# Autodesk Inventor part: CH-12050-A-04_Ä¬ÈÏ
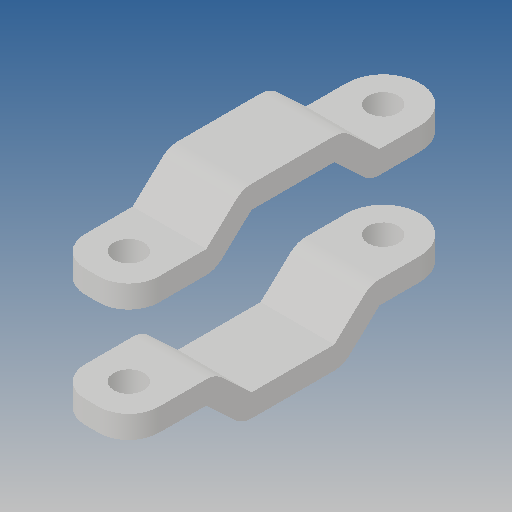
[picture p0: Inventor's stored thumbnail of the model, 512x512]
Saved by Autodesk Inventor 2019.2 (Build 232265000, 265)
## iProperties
Created: 2010-06
Part Number: CH-12050-A-04_Ä¬ÈÏ
Material: Ogólny
Document SubType Name: Modeling
Designer: CADENGINEERING4
Density: 1 g/cm^3
Appearance: Domyślna
Author: CADENGINEERING4
Revision Number: ÈÎºÎ
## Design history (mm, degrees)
feature "NONE"
feature "NONE:1"
node "Bryła1"
node "Bryła2"
